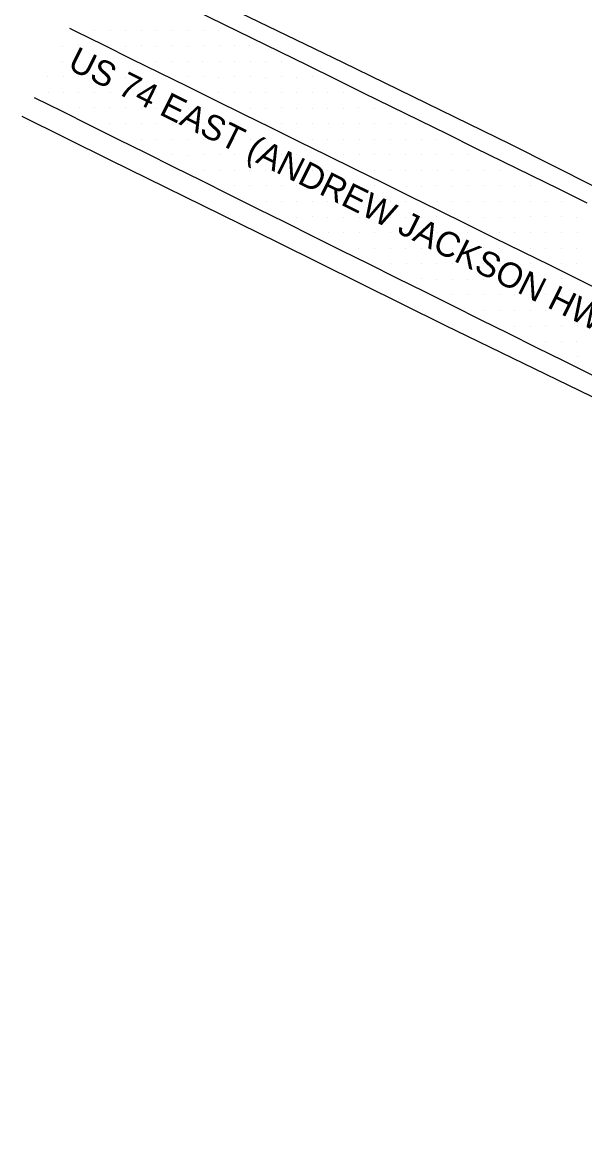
# Model space of a CAD drawing. Extents: x 2244337 to 2251208, y 199469 to 202984.
# Drawn here: x 2244337.5 to 2244427.8, y 202683.5 to 202861.5 of the extents above; entities that cross this region are included whole.
import ezdxf

# ---------------------------------------------------------------- set-up
doc = ezdxf.new("R2010")
doc.units = 0
for name, color, linetype in [('Exist DTM Scan Elevation Point', 7, 'Continuous'), ('Exist Roads EOP', 7, 'Continuous'), ('Exist Roads EOT', 7, 'Continuous'), ('Exist Roads Text', 7, 'Continuous')]:
    doc.layers.add(name, color=color, linetype=linetype)

msp = doc.modelspace()

# ---------------------------------------------------------------- linework, layer by layer
at = {"layer": 'Exist DTM Scan Elevation Point'}
for p, q in [((2244349.11, 202860.21), (2244349.11, 202860.21)), ((2244351.59, 202860.26), (2244351.59, 202860.26)), ((2244354.04, 202860.26), (2244354.04, 202860.26)), ((2244356.6, 202860.25), (2244356.6, 202860.25)), ((2244359.05, 202860.23), (2244359.05, 202860.23)), ((2244361.53, 202860.22), (2244361.53, 202860.22)), ((2244364.09, 202860.22), (2244364.09, 202860.22)), ((2244366.55, 202860.24), (2244366.55, 202860.24)), ((2244369.06, 202860.22), (2244369.06, 202860.22)), ((2244344.02, 202857.67), (2244344.02, 202857.67)), ((2244346.54, 202857.72), (2244346.54, 202857.72)), ((2244354.08, 202857.68), (2244354.08, 202857.68)), ((2244356.59, 202857.72), (2244356.59, 202857.72)), ((2244359.09, 202857.69), (2244359.09, 202857.69)), ((2244361.63, 202857.71), (2244361.63, 202857.71)), ((2244364.03, 202857.68), (2244364.03, 202857.68)), ((2244366.57, 202857.7), (2244366.57, 202857.7)), ((2244369.11, 202857.72), (2244369.11, 202857.72)), ((2244371.6, 202857.75), (2244371.6, 202857.75)), ((2244374.04, 202857.75), (2244374.04, 202857.75)), ((2244344.03, 202855.22), (2244344.03, 202855.22)), ((2244346.62, 202855.21), (2244346.62, 202855.21)), ((2244349.09, 202855.23), (2244349.09, 202855.23)), ((2244351.59, 202855.2), (2244351.59, 202855.2)), ((2244359.1, 202855.21), (2244359.1, 202855.21)), ((2244361.55, 202855.19), (2244361.55, 202855.19)), ((2244364.07, 202855.22), (2244364.07, 202855.22)), ((2244366.49, 202855.21), (2244366.49, 202855.21)), ((2244369.14, 202855.18), (2244369.14, 202855.18)), ((2244371.58, 202855.22), (2244371.58, 202855.22)), ((2244374.06, 202855.16), (2244374.06, 202855.16)), ((2244376.61, 202855.21), (2244376.61, 202855.21)), ((2244379.06, 202855.22), (2244379.06, 202855.22)), ((2244341.58, 202852.74), (2244341.58, 202852.74)), ((2244344.09, 202852.75), (2244344.09, 202852.75)), ((2244346.53, 202852.73), (2244346.53, 202852.73)), ((2244349.05, 202852.74), (2244349.05, 202852.74)), ((2244351.6, 202852.64), (2244351.6, 202852.64)), ((2244354.07, 202852.69), (2244354.07, 202852.69)), ((2244356.53, 202852.72), (2244356.53, 202852.72)), ((2244364.08, 202852.71), (2244364.08, 202852.71)), ((2244366.58, 202852.74), (2244366.58, 202852.74)), ((2244369.06, 202852.68), (2244369.06, 202852.68)), ((2244371.53, 202852.71), (2244371.53, 202852.71)), ((2244374.08, 202852.71), (2244374.08, 202852.71)), ((2244376.62, 202852.68), (2244376.62, 202852.68)), ((2244379.06, 202852.73), (2244379.06, 202852.73)), ((2244381.59, 202852.7), (2244381.59, 202852.7)), ((2244384.09, 202852.74), (2244384.09, 202852.74)), ((2244341.63, 202850.21), (2244341.63, 202850.21)), ((2244344.04, 202850.17), (2244344.04, 202850.17)), ((2244346.57, 202850.2), (2244346.57, 202850.2)), ((2244349.05, 202850.2), (2244349.05, 202850.2)), ((2244351.58, 202850.18), (2244351.58, 202850.18)), ((2244354.06, 202850.2), (2244354.06, 202850.2)), ((2244356.57, 202850.22), (2244356.57, 202850.22)), ((2244359.07, 202850.23), (2244359.07, 202850.23)), ((2244361.51, 202850.23), (2244361.51, 202850.23)), ((2244369.08, 202850.22), (2244369.08, 202850.22)), ((2244371.56, 202850.18), (2244371.56, 202850.18)), ((2244374.07, 202850.24), (2244374.07, 202850.24)), ((2244376.58, 202850.22), (2244376.58, 202850.22)), ((2244379.07, 202850.24), (2244379.07, 202850.24)), ((2244381.55, 202850.22), (2244381.55, 202850.22)), ((2244384.08, 202850.18), (2244384.08, 202850.18)), ((2244386.55, 202850.19), (2244386.55, 202850.19)), ((2244389.05, 202850.2), (2244389.05, 202850.2)), ((2244346.62, 202847.73), (2244346.62, 202847.73)), ((2244349.02, 202847.74), (2244349.02, 202847.74)), ((2244351.57, 202847.75), (2244351.57, 202847.75)), ((2244354.06, 202847.74), (2244354.06, 202847.74)), ((2244356.61, 202847.71), (2244356.61, 202847.71)), ((2244359.05, 202847.72), (2244359.05, 202847.72)), ((2244361.55, 202847.69), (2244361.55, 202847.69)), ((2244364.12, 202847.67), (2244364.12, 202847.67)), ((2244366.53, 202847.68), (2244366.53, 202847.68)), ((2244374.09, 202847.69), (2244374.09, 202847.69)), ((2244376.6, 202847.71), (2244376.6, 202847.71)), ((2244379.08, 202847.73), (2244379.08, 202847.73)), ((2244381.59, 202847.72), (2244381.59, 202847.72)), ((2244384.06, 202847.7), (2244384.06, 202847.7)), ((2244386.58, 202847.69), (2244386.58, 202847.69)), ((2244389.1, 202847.71), (2244389.1, 202847.71)), ((2244391.54, 202847.73), (2244391.54, 202847.73)), ((2244394.08, 202847.69), (2244394.08, 202847.69)), ((2244351.54, 202845.25), (2244351.54, 202845.25)), ((2244354.09, 202845.22), (2244354.09, 202845.22)), ((2244356.59, 202845.19), (2244356.59, 202845.19)), ((2244359.07, 202845.18), (2244359.07, 202845.18)), ((2244361.58, 202845.2), (2244361.58, 202845.2)), ((2244364.09, 202845.21), (2244364.09, 202845.21)), ((2244366.62, 202845.19), (2244366.62, 202845.19)), ((2244369.06, 202845.24), (2244369.06, 202845.24)), ((2244371.61, 202845.21), (2244371.61, 202845.21)), ((2244379.09, 202845.2), (2244379.09, 202845.2)), ((2244381.53, 202845.18), (2244381.53, 202845.18)), ((2244384.07, 202845.24), (2244384.07, 202845.24)), ((2244386.62, 202845.24), (2244386.62, 202845.24)), ((2244389.04, 202845.21), (2244389.04, 202845.21)), ((2244391.57, 202845.2), (2244391.57, 202845.2)), ((2244394.06, 202845.23), (2244394.06, 202845.23)), ((2244396.58, 202845.21), (2244396.58, 202845.21)), ((2244399.09, 202845.18), (2244399.09, 202845.18)), ((2244356.57, 202842.71), (2244356.57, 202842.71)), ((2244359.07, 202842.7), (2244359.07, 202842.7)), ((2244361.56, 202842.74), (2244361.56, 202842.74)), ((2244364.04, 202842.73), (2244364.04, 202842.73)), ((2244366.6, 202842.72), (2244366.6, 202842.72)), ((2244369.04, 202842.71), (2244369.04, 202842.71)), ((2244371.59, 202842.73), (2244371.59, 202842.73)), ((2244374.07, 202842.67), (2244374.07, 202842.67)), ((2244376.64, 202842.72), (2244376.64, 202842.72)), ((2244384.11, 202842.72), (2244384.11, 202842.72)), ((2244386.56, 202842.71), (2244386.56, 202842.71)), ((2244389.04, 202842.7), (2244389.04, 202842.7)), ((2244391.59, 202842.66), (2244391.59, 202842.66)), ((2244394.05, 202842.7), (2244394.05, 202842.7)), ((2244396.58, 202842.71), (2244396.58, 202842.71)), ((2244399.09, 202842.7), (2244399.09, 202842.7)), ((2244401.61, 202842.66), (2244401.61, 202842.66)), ((2244404.05, 202842.7), (2244404.05, 202842.7)), ((2244361.58, 202840.23), (2244361.58, 202840.23)), ((2244364.07, 202840.17), (2244364.07, 202840.17)), ((2244366.57, 202840.24), (2244366.57, 202840.24)), ((2244369.12, 202840.22), (2244369.12, 202840.22)), ((2244371.58, 202840.21), (2244371.58, 202840.21)), ((2244374.06, 202840.2), (2244374.06, 202840.2)), ((2244376.55, 202840.24), (2244376.55, 202840.24)), ((2244379.12, 202840.24), (2244379.12, 202840.24)), ((2244381.57, 202840.24), (2244381.57, 202840.24)), ((2244389.1, 202840.21), (2244389.1, 202840.21)), ((2244391.58, 202840.22), (2244391.58, 202840.22)), ((2244394.03, 202840.21), (2244394.03, 202840.21)), ((2244396.52, 202840.23), (2244396.52, 202840.23)), ((2244399.1, 202840.22), (2244399.1, 202840.22)), ((2244401.59, 202840.22), (2244401.59, 202840.22)), ((2244404.05, 202840.2), (2244404.05, 202840.2)), ((2244406.63, 202840.23), (2244406.63, 202840.23)), ((2244409.09, 202840.21), (2244409.09, 202840.21)), ((2244366.56, 202837.75), (2244366.56, 202837.75)), ((2244369.11, 202837.7), (2244369.11, 202837.7)), ((2244371.58, 202837.72), (2244371.58, 202837.72)), ((2244374.05, 202837.74), (2244374.05, 202837.74)), ((2244376.57, 202837.73), (2244376.57, 202837.73)), ((2244379.12, 202837.72), (2244379.12, 202837.72)), ((2244381.59, 202837.66), (2244381.59, 202837.66)), ((2244384.05, 202837.67), (2244384.05, 202837.67)), ((2244386.57, 202837.72), (2244386.57, 202837.72)), ((2244394.09, 202837.72), (2244394.09, 202837.72)), ((2244396.6, 202837.69), (2244396.6, 202837.69)), ((2244399.06, 202837.71), (2244399.06, 202837.71)), ((2244401.56, 202837.74), (2244401.56, 202837.74)), ((2244404.09, 202837.69), (2244404.09, 202837.69)), ((2244406.57, 202837.67), (2244406.57, 202837.67)), ((2244409.1, 202837.69), (2244409.1, 202837.69)), ((2244411.59, 202837.73), (2244411.59, 202837.73)), ((2244414.05, 202837.74), (2244414.05, 202837.74)), ((2244371.57, 202835.21), (2244371.57, 202835.21)), ((2244374.05, 202835.2), (2244374.05, 202835.2)), ((2244376.63, 202835.2), (2244376.63, 202835.2)), ((2244379.08, 202835.2), (2244379.08, 202835.2)), ((2244381.6, 202835.2), (2244381.6, 202835.2)), ((2244384.05, 202835.21), (2244384.05, 202835.21)), ((2244386.54, 202835.26), (2244386.54, 202835.26)), ((2244389.07, 202835.19), (2244389.07, 202835.19)), ((2244391.58, 202835.22), (2244391.58, 202835.22)), ((2244394.03, 202835.24), (2244394.03, 202835.24)), ((2244399.06, 202835.18), (2244399.06, 202835.18)), ((2244401.6, 202835.19), (2244401.6, 202835.19)), ((2244404.07, 202835.2), (2244404.07, 202835.2)), ((2244406.6, 202835.17), (2244406.6, 202835.17)), ((2244409.06, 202835.22), (2244409.06, 202835.22)), ((2244411.58, 202835.23), (2244411.58, 202835.23)), ((2244414.09, 202835.25), (2244414.09, 202835.25)), ((2244416.57, 202835.19), (2244416.57, 202835.19)), ((2244419.07, 202835.21), (2244419.07, 202835.21)), ((2244376.63, 202832.7), (2244376.63, 202832.7)), ((2244379.05, 202832.7), (2244379.05, 202832.7)), ((2244381.56, 202832.7), (2244381.56, 202832.7)), ((2244384.07, 202832.74), (2244384.07, 202832.74)), ((2244386.57, 202832.77), (2244386.57, 202832.77)), ((2244389.07, 202832.72), (2244389.07, 202832.72)), ((2244391.61, 202832.67), (2244391.61, 202832.67)), ((2244394.11, 202832.71), (2244394.11, 202832.71)), ((2244396.6, 202832.74), (2244396.6, 202832.74)), ((2244399.04, 202832.7), (2244399.04, 202832.7)), ((2244404.1, 202832.71), (2244404.1, 202832.71)), ((2244406.55, 202832.74), (2244406.55, 202832.74)), ((2244409.06, 202832.7), (2244409.06, 202832.7)), ((2244411.56, 202832.71), (2244411.56, 202832.71)), ((2244414.08, 202832.73), (2244414.08, 202832.73)), ((2244416.58, 202832.69), (2244416.58, 202832.69)), ((2244419.05, 202832.73), (2244419.05, 202832.73)), ((2244421.51, 202832.69), (2244421.51, 202832.69)), ((2244424.14, 202832.74), (2244424.14, 202832.74)), ((2244381.59, 202830.21), (2244381.59, 202830.21)), ((2244384.02, 202830.24), (2244384.02, 202830.24)), ((2244386.58, 202830.19), (2244386.58, 202830.19)), ((2244389.07, 202830.17), (2244389.07, 202830.17)), ((2244391.58, 202830.19), (2244391.58, 202830.19)), ((2244394.08, 202830.22), (2244394.08, 202830.22)), ((2244396.58, 202830.19), (2244396.58, 202830.19)), ((2244399.06, 202830.18), (2244399.06, 202830.18)), ((2244401.61, 202830.21), (2244401.61, 202830.21)), ((2244404.08, 202830.26), (2244404.08, 202830.26)), ((2244409.08, 202830.16), (2244409.08, 202830.16)), ((2244411.56, 202830.21), (2244411.56, 202830.21)), ((2244414.09, 202830.21), (2244414.09, 202830.21)), ((2244416.59, 202830.19), (2244416.59, 202830.19)), ((2244419.09, 202830.22), (2244419.09, 202830.22)), ((2244421.56, 202830.24), (2244421.56, 202830.24)), ((2244424.06, 202830.25), (2244424.06, 202830.25)), ((2244426.56, 202830.18), (2244426.56, 202830.18)), ((2244386.62, 202827.74), (2244386.62, 202827.74)), ((2244389.06, 202827.68), (2244389.06, 202827.68)), ((2244391.57, 202827.74), (2244391.57, 202827.74)), ((2244394.1, 202827.72), (2244394.1, 202827.72)), ((2244396.56, 202827.76), (2244396.56, 202827.76)), ((2244399.04, 202827.71), (2244399.04, 202827.71)), ((2244401.56, 202827.71), (2244401.56, 202827.71)), ((2244404.09, 202827.71), (2244404.09, 202827.71)), ((2244406.58, 202827.72), (2244406.58, 202827.72)), ((2244409.04, 202827.74), (2244409.04, 202827.74)), ((2244414.07, 202827.67), (2244414.07, 202827.67)), ((2244416.56, 202827.74), (2244416.56, 202827.74)), ((2244419.07, 202827.71), (2244419.07, 202827.71)), ((2244421.58, 202827.73), (2244421.58, 202827.73)), ((2244424.07, 202827.69), (2244424.07, 202827.69)), ((2244426.59, 202827.66), (2244426.59, 202827.66)), ((2244391.55, 202825.21), (2244391.55, 202825.21)), ((2244394.07, 202825.2), (2244394.07, 202825.2)), ((2244396.56, 202825.2), (2244396.56, 202825.2)), ((2244399.05, 202825.18), (2244399.05, 202825.18)), ((2244401.58, 202825.18), (2244401.58, 202825.18)), ((2244404.07, 202825.17), (2244404.07, 202825.17)), ((2244406.62, 202825.22), (2244406.62, 202825.22)), ((2244409.05, 202825.2), (2244409.05, 202825.2)), ((2244411.55, 202825.25), (2244411.55, 202825.25)), ((2244414.07, 202825.22), (2244414.07, 202825.22)), ((2244419.04, 202825.18), (2244419.04, 202825.18)), ((2244421.53, 202825.19), (2244421.53, 202825.19)), ((2244424.02, 202825.22), (2244424.02, 202825.22)), ((2244426.56, 202825.21), (2244426.56, 202825.21)), ((2244396.58, 202822.67), (2244396.58, 202822.67)), ((2244399.15, 202822.66), (2244399.15, 202822.66)), ((2244401.59, 202822.69), (2244401.59, 202822.69)), ((2244404.03, 202822.69), (2244404.03, 202822.69)), ((2244406.63, 202822.7), (2244406.63, 202822.7)), ((2244409.06, 202822.73), (2244409.06, 202822.73)), ((2244411.57, 202822.7), (2244411.57, 202822.7)), ((2244414.08, 202822.69), (2244414.08, 202822.69)), ((2244416.57, 202822.72), (2244416.57, 202822.72)), ((2244419.15, 202822.7), (2244419.15, 202822.7)), ((2244424.07, 202822.69), (2244424.07, 202822.69)), ((2244426.56, 202822.69), (2244426.56, 202822.69)), ((2244401.59, 202820.26), (2244401.59, 202820.26)), ((2244404.08, 202820.21), (2244404.08, 202820.21)), ((2244406.55, 202820.23), (2244406.55, 202820.23)), ((2244409.03, 202820.23), (2244409.03, 202820.23)), ((2244411.59, 202820.22), (2244411.59, 202820.22)), ((2244414.11, 202820.18), (2244414.11, 202820.18)), ((2244416.54, 202820.23), (2244416.54, 202820.23)), ((2244419.06, 202820.22), (2244419.06, 202820.22)), ((2244421.56, 202820.23), (2244421.56, 202820.23)), ((2244424.04, 202820.25), (2244424.04, 202820.25)), ((2244406.52, 202817.69), (2244406.52, 202817.69)), ((2244409.1, 202817.73), (2244409.1, 202817.73)), ((2244411.61, 202817.69), (2244411.61, 202817.69)), ((2244414.08, 202817.7), (2244414.08, 202817.7)), ((2244416.58, 202817.75), (2244416.58, 202817.75)), ((2244419.07, 202817.71), (2244419.07, 202817.71)), ((2244421.56, 202817.68), (2244421.56, 202817.68)), ((2244424.08, 202817.68), (2244424.08, 202817.68)), ((2244426.57, 202817.68), (2244426.57, 202817.68)), ((2244411.56, 202815.21), (2244411.56, 202815.21)), ((2244414.12, 202815.22), (2244414.12, 202815.22)), ((2244416.57, 202815.18), (2244416.57, 202815.18)), ((2244419.05, 202815.25), (2244419.05, 202815.25)), ((2244421.58, 202815.22), (2244421.58, 202815.22)), ((2244424.1, 202815.17), (2244424.1, 202815.17)), ((2244426.56, 202815.26), (2244426.56, 202815.26)), ((2244416.59, 202812.69), (2244416.59, 202812.69)), ((2244419.04, 202812.68), (2244419.04, 202812.68)), ((2244421.58, 202812.71), (2244421.58, 202812.71)), ((2244424.1, 202812.75), (2244424.1, 202812.75)), ((2244426.59, 202812.71), (2244426.59, 202812.71)), ((2244421.54, 202810.21), (2244421.54, 202810.21)), ((2244424.02, 202810.19), (2244424.02, 202810.19)), ((2244426.51, 202810.28), (2244426.51, 202810.28)), ((2244426.6, 202807.78), (2244426.6, 202807.78))]:
    msp.add_line(p, q, dxfattribs=at)
at = {"layer": 'Exist Roads EOP'}
for points in [[(2244351.85, 202873.14), (2244361.93, 202868.19), (2244388.91, 202855.07), (2244415.86, 202841.9), (2244442.67, 202828.42), (2244469.58, 202815.17), (2244496.52, 202801.95), (2244523.46, 202788.76), (2244550.26, 202775.27), (2244577.19, 202762.06), (2244604.11, 202748.8), (2244630.99, 202735.49), (2244657.92, 202722.28), (2244684.9, 202709.17), (2244711.73, 202695.73), (2244738.6, 202682.38), (2244765.5, 202669.1), (2244792.27, 202655.56), (2244819.23, 202642.39), (2244846.1, 202629.06), (2244872.91, 202615.58), (2244899.9, 202602.49), (2244926.63, 202588.88), (2244953.56, 202575.64)], [(2244943.48, 202547.28), (2244916.63, 202560.66), (2244889.68, 202573.83), (2244862.84, 202587.23), (2244835.88, 202600.4), (2244809.11, 202613.95), (2244782.35, 202627.51), (2244755.34, 202640.56), (2244728.54, 202654.04), (2244701.77, 202667.58), (2244674.67, 202680.46), (2244647.54, 202693.28), (2244620.76, 202706.79), (2244593.8, 202719.97), (2244566.9, 202733.24), (2244539.97, 202746.47), (2244513.27, 202760.09), (2244486.33, 202773.29), (2244459.38, 202786.53), (2244432.4, 202799.65), (2244405.41, 202812.75), (2244378.55, 202826.13), (2244351.63, 202839.37), (2244337.48, 202846.37)]]:
    msp.add_lwpolyline(points, dxfattribs=at)
at = {"layer": 'Exist Roads EOT'}
for points in [[(2244365.32, 202863.41), (2244369.8, 202861.21), (2244374.29, 202859), (2244378.78, 202856.8), (2244383.27, 202854.59), (2244387.75, 202852.39), (2244392.24, 202850.18), (2244396.72, 202847.97), (2244401.21, 202845.76), (2244405.7, 202843.55), (2244410.18, 202841.34), (2244414.67, 202839.13), (2244419.15, 202836.92), (2244423.64, 202834.72), (2244428.12, 202832.51)], [(2244345.09, 202860.54), (2244346.03, 202860.08), (2244350.51, 202857.86), (2244354.99, 202855.65), (2244359.48, 202853.44), (2244363.96, 202851.22), (2244368.44, 202849.01), (2244372.93, 202846.8), (2244377.41, 202844.58), (2244381.89, 202842.37), (2244386.38, 202840.16), (2244390.86, 202837.94), (2244395.34, 202835.73), (2244399.83, 202833.52), (2244404.31, 202831.3), (2244408.79, 202829.09), (2244413.28, 202826.88), (2244417.76, 202824.67), (2244422.25, 202822.45), (2244426.73, 202820.24), (2244431.21, 202818.03)], [(2244428.98, 202804.8), (2244424.5, 202807.02), (2244420.02, 202809.25), (2244415.55, 202811.48), (2244411.07, 202813.71), (2244406.6, 202815.94), (2244402.12, 202818.17), (2244397.65, 202820.4), (2244393.17, 202822.62), (2244388.69, 202824.85), (2244384.22, 202827.08), (2244379.74, 202829.31), (2244375.27, 202831.54), (2244370.79, 202833.77), (2244366.31, 202836), (2244361.84, 202838.23), (2244357.36, 202840.46), (2244352.89, 202842.69), (2244348.41, 202844.91), (2244343.94, 202847.14), (2244339.46, 202849.37)]]:
    msp.add_lwpolyline(points, dxfattribs=at)

# ---------------------------------------------------------------- texts
at = {"layer": 'Exist Roads Text'}
msp.add_text("US 74 EAST (ANDREW JACKSON HWY)        30'  PAVED", height=4.02, rotation=333.5317, dxfattribs=at).set_placement((2244344.59, 202854.1))

doc.saveas('drawing.dxf')
